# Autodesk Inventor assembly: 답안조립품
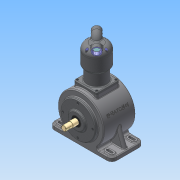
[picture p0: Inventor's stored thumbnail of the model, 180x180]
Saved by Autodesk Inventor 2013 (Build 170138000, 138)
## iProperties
Created: 2015-06
Part Number: 답안조립품
Document SubType Name: Assembly
Designer: Administrator
Author: Administrator
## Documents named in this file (15)
- C:\Users\Administrator\Desktop\450606V1015\답안조립품.iam
- C:\Users\Administrator\Desktop\450606V1015\본체.ipt
- C:\Users\Administrator\Desktop\450606V1015\메인 크랭크 축-구동부.ipt
- C:\Users\Administrator\Desktop\450606V1015\M4x0.7.ipt
- C:\Users\Administrator\Desktop\450606V1015\M5x0.8.ipt
- C:\Users\Administrator\Desktop\450606V1015\메인커버.ipt
- C:\Users\Administrator\Desktop\450606V1015\베어링 6204.ipt
- C:\Users\Administrator\Desktop\450606V1015\베어링 NA 4902.ipt
- C:\Users\Administrator\Desktop\450606V1015\실린더.ipt
- C:\Users\Administrator\Desktop\450606V1015\실린더헤드.ipt
- C:\Users\Administrator\Desktop\450606V1015\오일실.ipt
- C:\Users\Administrator\Desktop\450606V1015\커넥팅 로드.ipt
- C:\Users\Administrator\Desktop\450606V1015\크랭크 서브축.ipt
- C:\Users\Administrator\Desktop\450606V1015\피스톤 핀.ipt
- C:\Users\Administrator\Desktop\450606V1015\피스톤.ipt
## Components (14 placed, 4 different names)
1. 피스톤 핀:1
2. 피스톤:1
3. M4x0.7:1
4. M4x0.7:3
5. M4x0.7:4
6. M4x0.7:5
7. M4x0.7:2
8. M4x0.7:6
9. M4x0.7:7
10. M4x0.7:8
11. M5x0.8:1
12. M5x0.8:2
13. M5x0.8:3
14. M5x0.8:4
